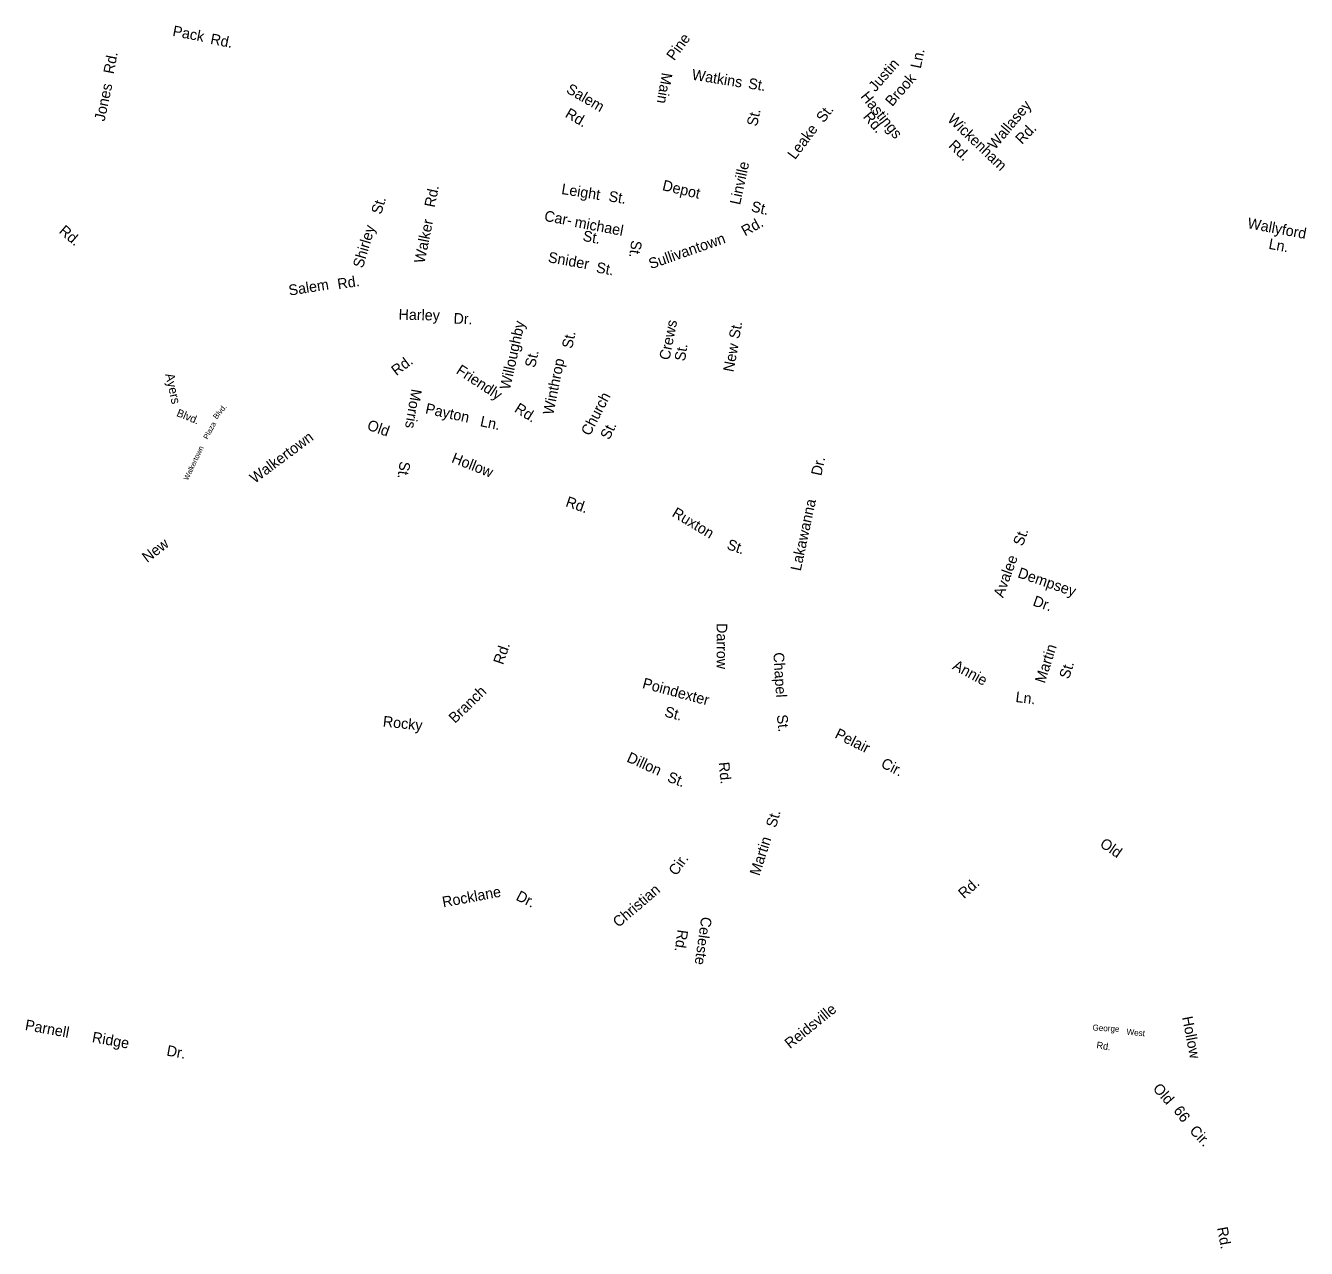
# Model space of a CAD drawing. Extents: x 1654773 to 2116434, y 680831 to 888488.
# Drawn here: x 1654773 to 1658337, y 885084 to 888488 of the extents above; entities that cross this region are included whole.
import ezdxf

# ---------------------------------------------------------------- set-up
doc = ezdxf.new("R2010")
doc.units = 0
for name, color, linetype in [('Exist Road Non-System Type 51 Label', 7, 'Continuous'), ('Exist Road Primary NC Label', 7, 'Continuous'), ('Exist Road Primary US Label', 7, 'Continuous'), ('Exist Road Secondary Type 51 Label', 7, 'Continuous')]:
    doc.layers.add(name, color=color, linetype=linetype)

msp = doc.modelspace()

# ---------------------------------------------------------------- texts
at = {"layer": 'Exist Road Non-System Type 51 Label'}
for s, height, rotation, p in [('Rd.', 29.69, 79.0174, (1655017.8, 888351.8)), ('Justin', 29.69, 48.8819, (1657137.7, 888301.8)), ('Ln.', 29.69, 78.1469, (1657263.7, 888366.9)), ('Watkins', 29.69, 350.8393, (1656625.3, 888337.8)), ('Brook', 29.69, 48.8819, (1657184.4, 888261)), ('Jones', 29.69, 78.0263, (1654992.5, 888220.2)), ('Salem', 29.69, 329.841, (1656274.9, 888302.9)), ('St.', 29.69, 350.8393, (1656782.1, 888313.2)), ('Hastings', 29.69, 309.1302, (1657094.6, 888290)), ('Rd.', 29.69, 329.841, (1656271.8, 888234.8)), ('St.', 29.69, 77.6398, (1656808.1, 888206)), ('St.', 29.69, 52.6602, (1656993.7, 888215.7)), ('Rd.', 29.69, 310.2861, (1657101.6, 888233.3)), ('Wallasey', 29.69, 50.1732, (1657470.3, 888140.9)), ('Leake', 29.69, 53.2296, (1656914.1, 888113.1)), ('Wickenham', 29.69, 316.38, (1657336, 888224.6)), ('Rd.', 29.69, 46.3361, (1657545.6, 888155.6)), ('Rd.', 29.69, 316.2572, (1657339.1, 888151.6)), ('Linville', 29.69, 77.6961, (1656761, 887987.4)), ('Leight', 29.69, 350.8825, (1656262.4, 888019.4)), ('Depot', 29.69, 346.6215, (1656542.8, 888030.2)), ('St.', 29.69, 73.2605, (1655762.1, 887960.5)), ('St.', 29.69, 350.8825, (1656393.6, 887999.2)), ('St.', 29.69, 346.6323, (1656790, 887971.4)), ('Car-', 29.69, 349.3782, (1656214.5, 887944.7)), ('Shirley', 29.69, 73.2605, (1655711.1, 887811)), ('michael', 29.69, 349.3782, (1656298.9, 887927.7)), ('St.', 29.69, 348.8563, (1656321.5, 887889.3)), ('Snider', 29.69, 349.7611, (1656225, 887829.6)), ('St.', 29.69, 349.7611, (1656359, 887801)), ('Rd.', 29.69, 9.059, (1655642.8, 887753.6)), ('Salem', 29.69, 8.9552, (1655507, 887736.2)), ('Harley', 29.69, 358.733, (1655810.5, 887669.3)), ('Dr.', 29.69, 357.8383, (1655963.2, 887658.4)), ('Willoughby', 29.69, 77.5731, (1656120.6, 887472.7)), ('Crews', 29.69, 78.7848, (1656564.5, 887555.3)), ('St.', 29.69, 79.312, (1656758.5, 887614.5)), ('St.', 29.69, 78.1471, (1656293.7, 887587.3)), ('New', 29.69, 79.312, (1656742.5, 887522.2)), ('St.', 29.69, 77.5731, (1656190.5, 887534.1)), ('St.', 29.69, 80.8271, (1656607.6, 887552.6)), ('Friendly', 29.69, 326.664, (1655968.5, 887521.6)), ('Winthrop', 29.69, 78.4515, (1656240.9, 887402.7)), ('Ayers', 25.29, 282.361, (1655161.3, 887517.2)), ('Morris', 29.69, 260.5214, (1655846.7, 887477.9)), ('Church', 29.69, 62.7239, (1656343, 887343.9)), ('Blvd.', 14.84, 50.158, (1655304.3, 887391.1)), ('Payton', 29.69, 347.7356, (1655883.3, 887408.6)), ('Rd.', 29.69, 327.8677, (1656130.7, 887414.6)), ('Blvd.', 21.67, 337.7686, (1655191, 887401.7)), ('Ln.', 29.69, 347.7356, (1656035.9, 887373.2)), ('Plaza', 14.82, 61.7922, (1655279.2, 887334.8)), ('St.', 29.69, 63.5638, (1656396.7, 887333)), ('Walkertown', 14.24, 64.558, (1655224.7, 887220.8)), ('St.', 29.69, 262.3533, (1655814.3, 887276.2)), ('Dr.', 29.69, 77.8072, (1656987.1, 887233.1)), ('Ruxton', 29.69, 329.0555, (1656569.2, 887123.4)), ('Lakawanna', 29.69, 77.8072, (1656929.7, 886968.1)), ('St.', 29.69, 69.9078, (1657547.5, 887037.1)), ('St.', 29.69, 340.7598, (1656721.9, 887031.6)), ('Avalee', 29.69, 70.0689, (1657492.9, 886893.5)), ('Dempsey', 29.69, 340.9404, (1657531.4, 886952.7)), ('Dr.', 29.69, 340.9404, (1657573.6, 886874.2)), ('Martin', 29.69, 72.2306, (1657609, 886655.3)), ('Chapel', 29.69, 273.4606, (1656853.6, 886742.4)), ('Annie', 29.69, 331.3649, (1657349.8, 886698)), ('St.', 29.69, 72.2306, (1657676.3, 886667.3)), ('Poindexter', 29.69, 344.9682, (1656487.2, 886644.4)), ('Ln.', 29.69, 352.9575, (1657526.5, 886605.2)), ('St.', 29.69, 344.9682, (1656548.6, 886565.3)), ('St.', 29.69, 276.6057, (1656862.9, 886568.5)), ('Pelair', 29.69, 333.4243, (1657022.4, 886506.7)), ('Dillon', 29.69, 335.7317, (1656443.3, 886439.9)), ('Cir.', 29.69, 333.4243, (1657150.7, 886424.6)), ('St.', 29.69, 339.1257, (1656556.1, 886384.6)), ('St.', 29.69, 73.866, (1656860.8, 886253.3)), ('Martin', 29.69, 72.2873, (1656815, 886119.5)), ('Cir.', 29.69, 54.6784, (1656583.7, 886119.4)), ('Rocklane', 29.69, 10.5845, (1655935, 886033.2)), ('Dr.', 29.69, 333.1343, (1656135.1, 886055.2)), ('Christian', 29.69, 40.6579, (1656422.6, 885975.9)), ('Celeste', 29.69, 261.9583, (1656653.4, 886008.4)), ('Rd.', 29.69, 261.9583, (1656587.3, 885972.6)), ('Parnell', 29.69, 349.6654, (1654769.6, 885692.4)), ('Ridge', 29.69, 349.766, (1654956.1, 885658.4)), ('Dr.', 29.69, 349.766, (1655163.5, 885621))]:
    msp.add_text(s, height=height, rotation=rotation, dxfattribs=at).set_placement(p)
at = {"layer": 'Exist Road Primary NC Label'}
for s, rotation, p in [('Rd.', 319.5129, (1654863.4, 887912.7)), ('Old', 340.5166, (1655720.8, 887364.1)), ('Hollow', 338.4864, (1655955.8, 887272.8)), ('Rd.', 340.8777, (1656273.4, 887150.5)), ('Old', 325.4855, (1657759.9, 886204.4)), ('Hollow', 280.9897, (1657991, 885727.3)), ('Rd.', 280.3749, (1658088.4, 885141.2))]:
    msp.add_text(s, height=29.69, rotation=rotation, dxfattribs=at).set_placement(p)
at = {"layer": 'Exist Road Primary US Label'}
for s, rotation, p in [('Main', 260.1929, (1656543.7, 888358.4)), ('St.', 261.9663, (1656458.8, 887891.6)), ('Rd.', 37.1347, (1655804.5, 887511.9)), ('Walkertown', 36.798, (1655410.5, 887212.2)), ('New', 37.4297, (1655111.1, 886991.7)), ('Rd.', 41.7653, (1657384.3, 886055.9)), ('Reidsville', 38.9258, (1656900, 885638.3))]:
    msp.add_text(s, height=29.69, rotation=rotation, dxfattribs=at).set_placement(p)
at = {"layer": 'Exist Road Secondary Type 51 Label'}
for s, height, rotation, p in [('Pack', 29.69, 348.9399, (1655180.1, 888459.5)), ('Rd.', 29.69, 348.9399, (1655285.2, 888437.4)), ('Pine', 29.69, 54.1261, (1656577.7, 888388.4)), ('Rd.', 29.69, 78.4067, (1655911, 887980.3)), ('Walker', 29.69, 78.4067, (1655882.5, 887824.5)), ('Rd.', 29.69, 28.9267, (1656774.9, 887901)), ('Wallyford', 29.69, 349.312, (1658171.3, 887924.5)), ('Sullivantown', 29.688, 19.3787, (1656512.7, 887809.8)), ('Ln.', 29.69, 349.312, (1658230.3, 887866.9)), ('Darrow', 29.69, 270.2045, (1656695.7, 886824.6)), ('Rd.', 29.69, 71.0225, (1656101.4, 886707)), ('Branch', 29.69, 44.2724, (1655967.6, 886543.9)), ('Rocky', 29.69, 353.7619, (1655765.9, 886537.1)), ('Rd.', 29.69, 275.2778, (1656701.5, 886436.8)), ('George', 16.87, 356.7746, (1657741.4, 885690.6)), ('West', 16.87, 354.4039, (1657835.8, 885679.1)), ('Rd.', 19.06, 351.2118, (1657751.8, 885641.2)), ('Old', 29.69, 311.7667, (1657907.9, 885527.6)), ('66', 29.69, 306.6225, (1657965.7, 885467.4)), ('Cir.', 29.69, 313.4419, (1658009.8, 885409.7))]:
    msp.add_text(s, height=height, rotation=rotation, dxfattribs=at).set_placement(p)

doc.saveas('drawing.dxf')
